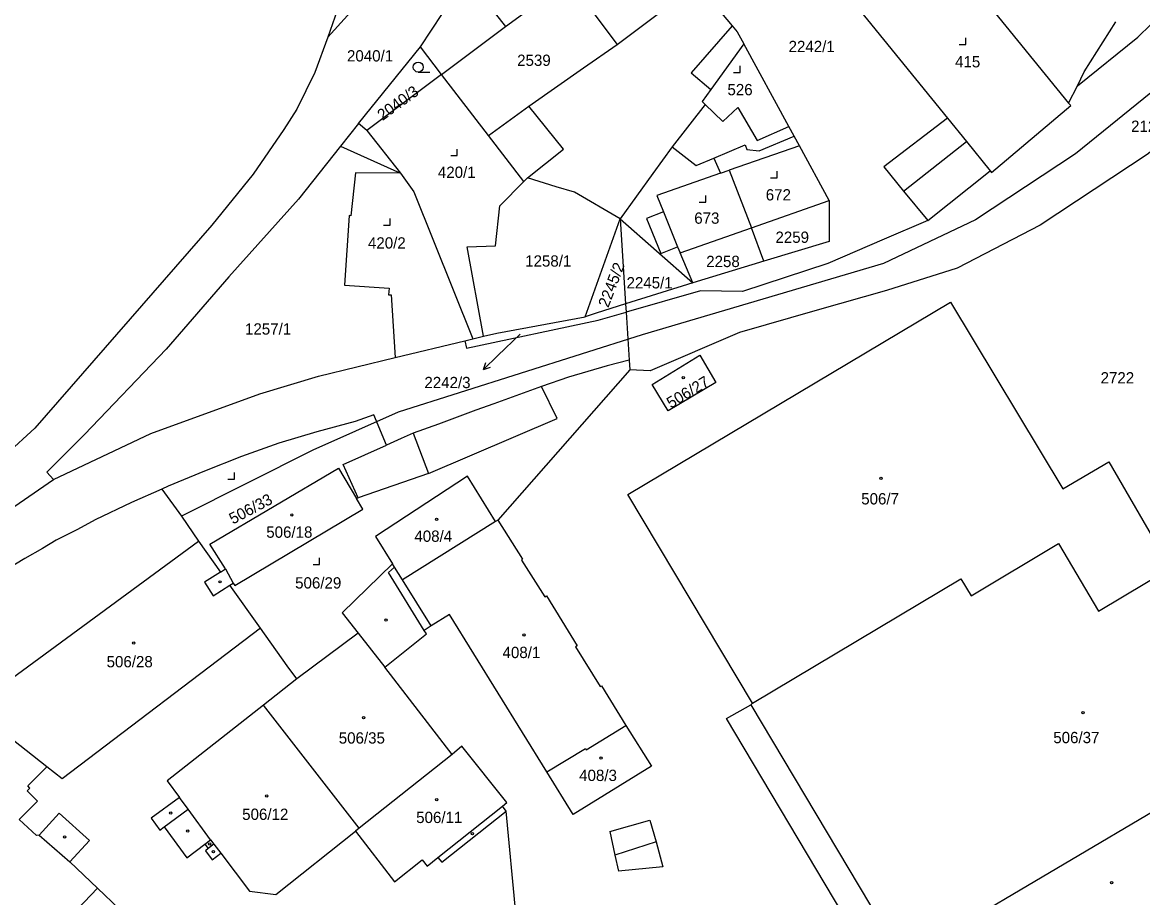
# Model space of a CAD drawing. Extents: x -679220 to -673243, y -1075091 to -1066557.
# Drawn here: x -677024.2 to -676855.4, y -1070716.7 to -1070584.9 of the extents above; entities that cross this region are included whole.
import ezdxf

# ---------------------------------------------------------------- set-up
doc = ezdxf.new("R2010")
doc.units = 0
for name, color, linetype in [('Hranice parcel', 7, 'Continuous'), ('Parcelní čísla', 7, 'Continuous'), ('Pop  PČ popisy', 7, 'Continuous'), ('Poz předměty', 7, 'Continuous'), ('Vnitřní kresba', 7, 'Continuous'), ('Značky budov', 7, 'Continuous'), ('Značky kultur', 7, 'Continuous')]:
    doc.layers.add(name, color=color, linetype=linetype)

msp = doc.modelspace()

# ---------------------------------------------------------------- linework, layer by layer
at = {"layer": 'Hranice parcel'}
for p, q in [((-676978.18, -1070587.09), (-676951.98, -1070558.36)), ((-676973.53, -1070600.09), (-676964.18, -1070588.55)), ((-676961.04, -1070592.7), (-676964.18, -1070588.55)), ((-676973.53, -1070600.09), (-676976.25, -1070603.52)), ((-676976.25, -1070603.52), (-676967.22, -1070607.61)), ((-676914.34, -1070615.81), (-676902.64, -1070611.7)), ((-676939.41, -1070629.21), (-676934.11, -1070614.47)), ((-676934.11, -1070614.47), (-676933.32, -1070627.3)), ((-676934.11, -1070614.47), (-676923.2, -1070624.1)), ((-676912.49, -1070620.85), (-676914.34, -1070615.81)), ((-676912.49, -1070620.85), (-676923.2, -1070624.1)), ((-676923.2, -1070624.1), (-676933.32, -1070627.3)), ((-676933.32, -1070627.3), (-676933.24, -1070628.54)), ((-676933.24, -1070628.54), (-676932.79, -1070635.78)), ((-676968.03, -1070635.38), (-676957.53, -1070632.85)), ((-676957.53, -1070632.85), (-676956.31, -1070632.56)), ((-676956.31, -1070632.56), (-676954.7, -1070632.17)), ((-676932.79, -1070635.78), (-676932.64, -1070637.23)), ((-676932.64, -1070637.23), (-676952.56, -1070659.85)), ((-676952.56, -1070659.85), (-676952.9, -1070660.06)), ((-676997.65, -1070663.02), (-676994.33, -1070667.68)), ((-676968.1, -1070666.95), (-676968.41, -1070666.46)), ((-676988.3, -1070676.13), (-676992.91, -1070669.66)), ((-676982.84, -1070683.78), (-676987.83, -1070687.72)), ((-676973.42, -1070706.26), (-676987.83, -1070687.72)), ((-676914.43, -1070687.67), (-676914.21, -1070687.45)), ((-677020.51, -1070697.05), (-677027.74, -1070691.36)), ((-676959.41, -1070695.16), (-676973.42, -1070706.26)), ((-676949.82, -1070719.08), (-676951.28, -1070703.69)), ((-676973.42, -1070706.26), (-676973.99, -1070706.71))]:
    msp.add_line(p, q, dxfattribs=at)
for points in [[(-676972.95, -1070555), (-676976.41, -1070582.08), (-676978.18, -1070587.09)], [(-676865.23, -1070594.45), (-676856.14, -1070587.08), (-676844.4, -1070575.61), (-676832.6, -1070560.19)], [(-676957.23, -1070578.13), (-676951.41, -1070585.47), (-676941.86, -1070578.5), (-676929.46, -1070569.32), (-676922.03, -1070578.74), (-676922.96, -1070579.44), (-676922.39, -1070580.2), (-676921.95, -1070579.86), (-676920.25, -1070582.13), (-676920.05, -1070581.97), (-676919.41, -1070582.84)], [(-676964.18, -1070588.55), (-676959.24, -1070580.98), (-676957.23, -1070578.13)], [(-676832.62, -1070579.59), (-676845.84, -1070597.03), (-676854.57, -1070604.7), (-676870.87, -1070615.42), (-676883.37, -1070621.89), (-676893.98, -1070625.27), (-676904.43, -1070628.25), (-676916.13, -1070631.61), (-676929.61, -1070637.37), (-676932.64, -1070637.23)], [(-676899.29, -1070581.47), (-676884.81, -1070599.31), (-676894.42, -1070606.66), (-676891.42, -1070610.32), (-676887.79, -1070614.74)], [(-676919.41, -1070582.84), (-676917.26, -1070585.38), (-676916.48, -1070586.31), (-676915.48, -1070588.11)], [(-676865.23, -1070594.45), (-676864.21, -1070592.33), (-676859.47, -1070584.79)], [(-676978.18, -1070587.09), (-676980.11, -1070592.44), (-676982.81, -1070597.93), (-676984.8, -1070601.01), (-676989.42, -1070607.76), (-676995.65, -1070615.43), (-677022.29, -1070646), (-677026.55, -1070649.95), (-677029.32, -1070647.99)], [(-676915.48, -1070588.11), (-676920.47, -1070594.99), (-676921.77, -1070596.78), (-676921.31, -1070597.23), (-676926.31, -1070603.63)], [(-676907.91, -1070602.03), (-676908.69, -1070600.58), (-676915.48, -1070588.11)], [(-676961.04, -1070592.7), (-676972.27, -1070601.18), (-676973.53, -1070600.09)], [(-676948.64, -1070608.85), (-676953.96, -1070601.92), (-676961.04, -1070592.7)], [(-676887.79, -1070614.74), (-676878.41, -1070607.25), (-676878.21, -1070607.5), (-676866.26, -1070597.41), (-676866.57, -1070597.02), (-676865.23, -1070594.45)], [(-676920, -1070605.31), (-676915.27, -1070603.33), (-676915.02, -1070604.04), (-676913.2, -1070604.2), (-676907.91, -1070602.03)], [(-676902.64, -1070611.7), (-676907.12, -1070603.47), (-676907.91, -1070602.03)], [(-676976.25, -1070603.52), (-676982.6, -1070611.51), (-676993.08, -1070623.23), (-677002.49, -1070634.12), (-677014.82, -1070646.97), (-677020.46, -1070652.65), (-677019.47, -1070653.76)], [(-676926.31, -1070603.63), (-676929.2, -1070607.62), (-676934.11, -1070614.47)], [(-676926.31, -1070603.63), (-676922.65, -1070606.42), (-676920, -1070605.31)], [(-676920, -1070605.31), (-676918.99, -1070607.6), (-676917.7, -1070607.15), (-676914.34, -1070615.81)], [(-676967.22, -1070607.61), (-676974.01, -1070607.54), (-676974.67, -1070614.02), (-676974.92, -1070613.99), (-676975.67, -1070624.47), (-676968.9, -1070624.9), (-676969.03, -1070625.94), (-676968.63, -1070625.94), (-676968.03, -1070635.38)], [(-676967.22, -1070607.61), (-676965.19, -1070610.42), (-676956.31, -1070632.56)], [(-676954.7, -1070632.17), (-676957.17, -1070618.68), (-676952.92, -1070618.54), (-676952.24, -1070612.51), (-676948.64, -1070608.85)], [(-676934.11, -1070614.47), (-676941.02, -1070610.47), (-676943.74, -1070609.67), (-676948.07, -1070608.29), (-676948.64, -1070608.85)], [(-676902.64, -1070611.7), (-676902.64, -1070617.86), (-676912.49, -1070620.85)], [(-676887.79, -1070614.74), (-676894.34, -1070617.52), (-676902.86, -1070621.19), (-676915.68, -1070625.42), (-676922.02, -1070625.3), (-676933.24, -1070628.54)], [(-676923.2, -1070624.1), (-676925.1, -1070619.58), (-676914.34, -1070615.81)], [(-676933.32, -1070627.3), (-676937.75, -1070628.7), (-676939.41, -1070629.21)], [(-676914.21, -1070687.45), (-676932.98, -1070656.02), (-676884.37, -1070627.01), (-676867.46, -1070655.15), (-676860.5, -1070651.1), (-676851.35, -1070666.86)], [(-676957.53, -1070632.85), (-676957.26, -1070633.96), (-676937.44, -1070629.76), (-676933.24, -1070628.54)], [(-676954.7, -1070632.17), (-676952.72, -1070631.69), (-676939.41, -1070629.21)], [(-676926.88, -1070643.42), (-676929.32, -1070639.42), (-676922.14, -1070635.03), (-676919.7, -1070639.14), (-676926.88, -1070643.42)], [(-677019.47, -1070653.76), (-677004.81, -1070646.81), (-676988.41, -1070640.83), (-676979.55, -1070638.15), (-676968.03, -1070635.38)], [(-676932.79, -1070635.78), (-676936.09, -1070636.63), (-676941.88, -1070638.32), (-676945.99, -1070639.71), (-676953.14, -1070642.34), (-676955.88, -1070643.31), (-676961.47, -1070645.41), (-676965.3, -1070646.77), (-676967.1, -1070647.58), (-676969.34, -1070648.57)], [(-676969.34, -1070648.57), (-676971.24, -1070644), (-676974.05, -1070644.98), (-676979.83, -1070646.54), (-676982.68, -1070647.39), (-676985.55, -1070648.28), (-676991.15, -1070650.27), (-676996.73, -1070652.47), (-677002.22, -1070654.77), (-677003.15, -1070655.19)], [(-676973.82, -1070656.6), (-676973.58, -1070656.52), (-676975.85, -1070651.5), (-676969.34, -1070648.57)], [(-676994.33, -1070667.68), (-676993.58, -1070667.21), (-676995.91, -1070663.49), (-676976.56, -1070652.05), (-676973.82, -1070656.6)], [(-676952.9, -1070660.06), (-676957.13, -1070653.25), (-676970.99, -1070662.33), (-676968.41, -1070666.46)], [(-677135.39, -1070729.77), (-677126.91, -1070726.13), (-677119.11, -1070722.08), (-677111.25, -1070717.42), (-677103.91, -1070713.3), (-677097.19, -1070709.11), (-677075.17, -1070692.52), (-677062.55, -1070683.44), (-677056.34, -1070679.02), (-677044.15, -1070670.16), (-677029.88, -1070660.86), (-677019.47, -1070653.76)], [(-677003.15, -1070655.19), (-677007.73, -1070657.23), (-677013.21, -1070659.83), (-677015.86, -1070661.26), (-677019.09, -1070662.86), (-677021.15, -1070664.15), (-677023.81, -1070665.65), (-677026.34, -1070667.21), (-677028.95, -1070668.79), (-677031.47, -1070670.4), (-677034.01, -1070671.98), (-677036.54, -1070673.73), (-677039.05, -1070675.44), (-677041.45, -1070677.28), (-677070.75, -1070698.39), (-677076.54, -1070702.6), (-677081.33, -1070706.06), (-677093, -1070715.15), (-677095.02, -1070716.41)], [(-677003.15, -1070655.19), (-677000.2, -1070659.28), (-676997.65, -1070663.02)], [(-676992.91, -1070669.66), (-676992.4, -1070669.34), (-676992.17, -1070669.72), (-676972.87, -1070658.19), (-676973.82, -1070656.6)], [(-676952.9, -1070660.06), (-676966.92, -1070668.84), (-676968.1, -1070666.95)], [(-676952.56, -1070659.85), (-676948.81, -1070665.77), (-676948.98, -1070665.88), (-676945.49, -1070671.41), (-676945.23, -1070671.25), (-676940.59, -1070678.79), (-676940.85, -1070678.95), (-676937.12, -1070684.94), (-676936.95, -1070684.84), (-676933.28, -1070690.83)], [(-677027.74, -1070691.36), (-677030.83, -1070687.38), (-676997.65, -1070663.02)], [(-676914.21, -1070687.45), (-676882.78, -1070668.69), (-676881.25, -1070671.25), (-676868.11, -1070663.41), (-676862.05, -1070673.56), (-676851.21, -1070667.09), (-676851.35, -1070666.86)], [(-676968.41, -1070666.46), (-676976.01, -1070673.83), (-676973.61, -1070676.87), (-676982.84, -1070683.78)], [(-676963.64, -1070676.47), (-676969.02, -1070667.73), (-676968.1, -1070666.95)], [(-676994.33, -1070667.68), (-676996.73, -1070669.2), (-676995.44, -1070671.25), (-676992.91, -1070669.66)], [(-676945.15, -1070697.81), (-676959.84, -1070674.09), (-676962.57, -1070675.8), (-676963.64, -1070676.47)], [(-676988.3, -1070676.13), (-677018.18, -1070698.84), (-677020.51, -1070697.05)], [(-676982.84, -1070683.78), (-676984.27, -1070681.84), (-676988.3, -1070676.13)], [(-676959.41, -1070695.16), (-676969.55, -1070682.02), (-676963.29, -1070677.02), (-676963.64, -1070676.47)], [(-676987.83, -1070687.72), (-677002.35, -1070699.14), (-677000.5, -1070701.65), (-677004.77, -1070704.79), (-677003.47, -1070706.56), (-677002.83, -1070706.09), (-676999.42, -1070710.75), (-676996.7, -1070708.68), (-676996.18, -1070709.36), (-676996.59, -1070709.68), (-676995.56, -1070711.04), (-676994.28, -1070710.06), (-676989.95, -1070715.75), (-676985.97, -1070716.27), (-676973.99, -1070706.71)], [(-676895.12, -1070728.36), (-676918.1, -1070689.75), (-676914.43, -1070687.67)], [(-676933.28, -1070690.83), (-676929.41, -1070696.92), (-676941.19, -1070704.21), (-676945.15, -1070697.81)], [(-676945.15, -1070697.81), (-676939.34, -1070694.28), (-676939.24, -1070694.45), (-676933.28, -1070690.83)], [(-676951.28, -1070703.69), (-676951.85, -1070702.96), (-676951.19, -1070702.43), (-676957.95, -1070693.93), (-676959.41, -1070695.16)], [(-677034.28, -1070697.59), (-677046.67, -1070710.74), (-677026.45, -1070729.62), (-677023.7, -1070726.67), (-677004.38, -1070736.72), (-676997.98, -1070729.55), (-677000.66, -1070726.99), (-676998.67, -1070724.91), (-677001.07, -1070722.57), (-677003.08, -1070724.67), (-677012.86, -1070715.31), (-677017.01, -1070711.34), (-677014.07, -1070708.12), (-677018.61, -1070704), (-677021.65, -1070707.35), (-677022.05, -1070707.36), (-677024.63, -1070704.99), (-677021.89, -1070702.22), (-677023.46, -1070700.67), (-677023.03, -1070700.24), (-677023.35, -1070699.92), (-677020.51, -1070697.05)], [(-676851.52, -1070702.41), (-676885.18, -1070722.27), (-676884.94, -1070722.68), (-676878.23, -1070734.06)], [(-676973.99, -1070706.71), (-676968.12, -1070714.35), (-676963.95, -1070711.03), (-676963.19, -1070711.99), (-676961.57, -1070710.69), (-676960.99, -1070711.42), (-676951.28, -1070703.69)]]:
    msp.add_lwpolyline(points, dxfattribs=at)
at = {"layer": 'Pop  PČ popisy'}
for p, q in [((-676949.18, -1070631.83), (-676952.55, -1070635.06)), ((-676952.55, -1070635.06), (-676954.71, -1070637.15)), ((-676954.71, -1070637.15), (-676954.34, -1070636.09)), ((-676954.71, -1070637.15), (-676953.64, -1070636.81))]:
    msp.add_line(p, q, dxfattribs=at)
at = {"layer": 'Poz předměty'}
for p, q in [((-676852.07, -1070593.8), (-676865.52, -1070604.68)), ((-676865.52, -1070604.68), (-676880.58, -1070614.6)), ((-676880.58, -1070614.6), (-676894.44, -1070621.21)), ((-676894.44, -1070621.21), (-676930.81, -1070631.96)), ((-676930.81, -1070631.96), (-676967.54, -1070643.6)), ((-676967.54, -1070643.6), (-676980.43, -1070649.32)), ((-676980.43, -1070649.32), (-677000.2, -1070659.28))]:
    msp.add_line(p, q, dxfattribs=at)
at = {"layer": 'Vnitřní kresba'}
for p, q in [((-676887.56, -1070571.26), (-676866.57, -1070597.02)), ((-676941.86, -1070578.5), (-676934.58, -1070588.21)), ((-676934.58, -1070588.21), (-676922.96, -1070579.44)), ((-676961.04, -1070592.7), (-676951.41, -1070585.47)), ((-676917.26, -1070585.38), (-676923.41, -1070592.49)), ((-676939.64, -1070591.72), (-676934.58, -1070588.21)), ((-676947.86, -1070597.47), (-676939.64, -1070591.72)), ((-676923.41, -1070592.49), (-676920.47, -1070594.99)), ((-676953.96, -1070601.92), (-676947.86, -1070597.47)), ((-676942.64, -1070603.99), (-676947.86, -1070597.47)), ((-676921.31, -1070597.23), (-676918.68, -1070599.82)), ((-676918.68, -1070599.82), (-676916.4, -1070597.68)), ((-676916.4, -1070597.68), (-676913.49, -1070602.69)), ((-676884.81, -1070599.31), (-676881.97, -1070602.83)), ((-676972.27, -1070601.18), (-676967.22, -1070607.61)), ((-676913.49, -1070602.69), (-676908.69, -1070600.58)), ((-676891.42, -1070610.32), (-676881.97, -1070602.83)), ((-676881.97, -1070602.83), (-676878.41, -1070607.25)), ((-676948.07, -1070608.29), (-676942.64, -1070603.99)), ((-676907.12, -1070603.47), (-676917.7, -1070607.15)), ((-676918.99, -1070607.6), (-676928.6, -1070610.94)), ((-676928.6, -1070610.94), (-676927.61, -1070613.39)), ((-676927.61, -1070613.39), (-676930.16, -1070614.42)), ((-676930.16, -1070614.42), (-676928.02, -1070619.71)), ((-676927.61, -1070613.39), (-676925.47, -1070618.67)), ((-676928.02, -1070619.71), (-676925.47, -1070618.67)), ((-676925.47, -1070618.67), (-676925.1, -1070619.58)), ((-676943.6, -1070644.57), (-676945.99, -1070639.71)), ((-676963, -1070652.86), (-676943.6, -1070644.57)), ((-676965.3, -1070646.77), (-676963, -1070652.86)), ((-676963, -1070652.86), (-676973.58, -1070656.52)), ((-676993.58, -1070667.21), (-676992.4, -1070669.34)), ((-676962.57, -1070675.8), (-676966.92, -1070668.84)), ((-676973.61, -1070676.87), (-676969.55, -1070682.02)), ((-676914.43, -1070687.67), (-676891.45, -1070726.25)), ((-676999.2, -1070703.43), (-677000.5, -1070701.65)), ((-677002.83, -1070706.09), (-676999.2, -1070703.43)), ((-676995.83, -1070708.02), (-676999.2, -1070703.43)), ((-676961.57, -1070710.69), (-676951.85, -1070702.96)), ((-676935.7, -1070706.8), (-676929.64, -1070705.07)), ((-676929.64, -1070705.07), (-676928.68, -1070708.31)), ((-677021.65, -1070707.35), (-677017.01, -1070711.34)), ((-676935.7, -1070706.8), (-676934.9, -1070710.32)), ((-676996.7, -1070708.68), (-676995.83, -1070708.02)), ((-676995.31, -1070708.7), (-676996.18, -1070709.36)), ((-676995.83, -1070708.02), (-676995.31, -1070708.7)), ((-676995.31, -1070708.7), (-676994.28, -1070710.06)), ((-676928.68, -1070708.31), (-676934.9, -1070710.32)), ((-676928.68, -1070708.31), (-676927.67, -1070712.11)), ((-676934.9, -1070710.32), (-676934.35, -1070712.73)), ((-676927.67, -1070712.11), (-676934.35, -1070712.73)), ((-677023.7, -1070726.67), (-677012.86, -1070715.31))]:
    msp.add_line(p, q, dxfattribs=at)
at = {"layer": 'Značky budov'}
for centre in [(-676924.61, -1070638.4), (-676894.85, -1070653.57), (-676983.58, -1070659.09), (-676961.78, -1070659.73), (-676994.4, -1070669.16), (-676969.38, -1070674.93), (-676948.61, -1070677.16), (-677007.39, -1070678.38), (-676864.39, -1070688.89), (-676972.78, -1070689.61), (-676937, -1070695.72), (-676987.36, -1070701.41), (-676961.75, -1070701.96), (-677001.83, -1070704), (-677017.82, -1070707.6), (-676999.27, -1070706.71), (-676956.37, -1070707.1), (-676995.95, -1070708.64), (-676995.4, -1070709.81), (-676860.1, -1070714.47)]:
    msp.add_circle(centre, 0.175, dxfattribs=at)
at = {"layer": 'Značky kultur'}
for p, q in [((-676882.05, -1070588.19), (-676882.05, -1070587.19)), ((-676883.05, -1070588.19), (-676882.05, -1070588.19)), ((-676964.54, -1070592.36), (-676962.79, -1070592.36)), ((-676917.05, -1070592.42), (-676916.05, -1070592.42)), ((-676916.05, -1070592.42), (-676916.05, -1070591.42)), ((-676958.65, -1070604.95), (-676958.65, -1070603.95)), ((-676959.65, -1070604.95), (-676958.65, -1070604.95)), ((-676910.49, -1070608.27), (-676910.49, -1070607.27)), ((-676911.49, -1070608.27), (-676910.49, -1070608.27)), ((-676921.24, -1070611.94), (-676921.24, -1070610.94)), ((-676922.24, -1070611.94), (-676921.24, -1070611.94)), ((-676968.76, -1070615.41), (-676968.76, -1070614.41)), ((-676969.76, -1070615.41), (-676968.76, -1070615.41)), ((-676992.2, -1070653.7), (-676992.2, -1070652.7)), ((-676993.2, -1070653.7), (-676992.2, -1070653.7)), ((-676980.39, -1070666.55), (-676979.39, -1070666.55)), ((-676979.39, -1070666.55), (-676979.39, -1070665.55))]:
    msp.add_line(p, q, dxfattribs=at)
msp.add_circle((-676964.54, -1070591.61), 0.75, dxfattribs=at)

# ---------------------------------------------------------------- texts
at = {"layer": 'Parcelní čísla'}
for s, p in [('2242/1', (-676908.75, -1070589.35)), ('2040/1', (-676975.27, -1070590.76)), ('2539', (-676949.64, -1070591.43)), ('415', (-676883.67, -1070591.65)), ('526', (-676917.96, -1070595.85)), ('2122/1', (-676857.16, -1070601.37)), ('420/1', (-676961.58, -1070608.3)), ('672', (-676912.19, -1070611.7)), ('673', (-676922.96, -1070615.21)), ('2259', (-676910.73, -1070618.09)), ('420/2', (-676972.11, -1070618.95)), ('1258/1', (-676948.43, -1070621.67)), ('2258', (-676921.16, -1070621.74)), ('2245/1', (-676933.16, -1070624.95)), ('1257/1', (-676990.63, -1070631.91)), ('2242/3', (-676963.61, -1070639.98)), ('2722', (-676861.75, -1070639.27)), ('506/7', (-676897.81, -1070657.5)), ('506/18', (-676987.43, -1070662.52)), ('408/4', (-676965.12, -1070663.13)), ('506/29', (-676983.08, -1070670.17)), ('408/1', (-676951.84, -1070680.65)), ('506/28', (-677011.48, -1070682.04)), ('506/35', (-676976.51, -1070693.53)), ('506/37', (-676868.88, -1070693.47)), ('408/3', (-676940.3, -1070699.17)), ('506/12', (-676991.06, -1070705.03)), ('506/11', (-676964.85, -1070705.5))]:
    msp.add_text(s, height=1.7, dxfattribs=at).set_placement(p)
for s, rotation, p in [('2040/3', 36, (-676969.92, -1070599.74)), ('2245/2', 69, (-676935.91, -1070627.95)), ('506/27', 31, (-676926.47, -1070643.09)), ('506/33', 28, (-676992.46, -1070660.54))]:
    msp.add_text(s, height=1.7, rotation=rotation, dxfattribs=at).set_placement(p)

doc.saveas('drawing.dxf')
